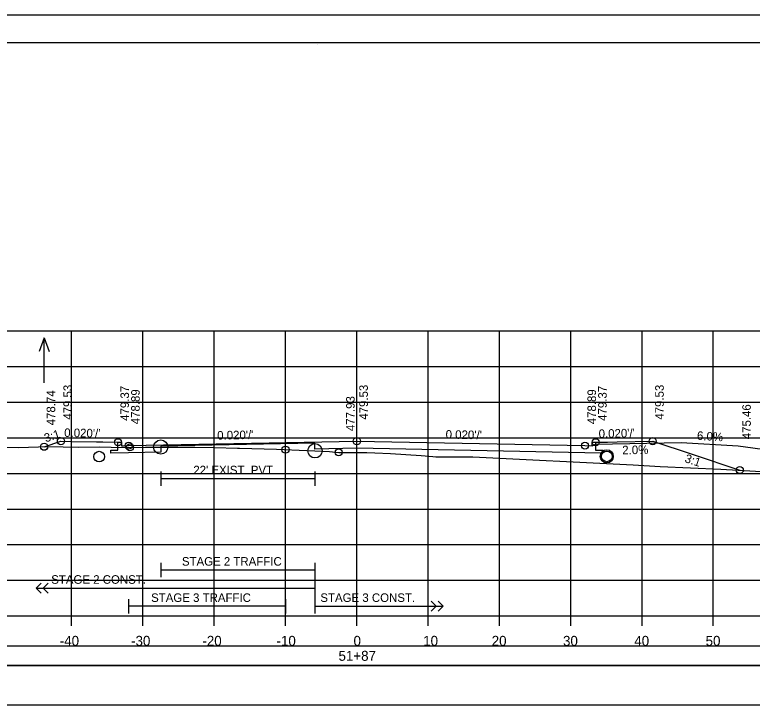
# Model space of a CAD drawing. Extents: x 1371057 to 1372761, y 380005 to 390517.
# Drawn here: x 1371512.9 to 1371616.3, y 383320.8 to 383418.5 of the extents above; entities that cross this region are included whole.
import ezdxf

# ---------------------------------------------------------------- set-up
doc = ezdxf.new("R2010")
doc.units = 0
for name, color, linetype in [('R_Alt Surface', 7, 'Continuous'), ('R_Axis', 7, 'Continuous'), ('R_Axis Annot', 7, 'Continuous'), ('R_Border', 7, 'Continuous'), ('R_Detour', 7, 'Continuous'), ('R_Dimension', 7, 'Continuous'), ('R_Drive', 7, 'Continuous'), ('R_Exist Surface', 7, 'Continuous'), ('R_Fin Surface', 7, 'Continuous'), ('R_Grid', 7, 'Continuous'), ('R_No Plot', 7, 'Continuous'), ('R_Striping', 7, 'Continuous'), ('R_Water', 7, 'Continuous'), ('R_Water Annot', 7, 'Continuous'), ('R_Xsect Elev', 7, 'Continuous'), ('R_Xsect Slope', 7, 'Continuous')]:
    doc.layers.add(name, color=color, linetype=linetype)

msp = doc.modelspace()

# ---------------------------------------------------------------- linework, layer by layer
at = {"layer": 'R_Alt Surface'}
for points in [[(1371594.37, 383358.5), (1371594.37, 383357.42), (1371595.37, 383357.4), (1371595.37, 383356.97), (1371592.87, 383357.02), (1371560.87, 383357.66), (1371555, 383357.54), (1371555, 383358.37), (1371533.37, 383357.94), (1371533.37, 383357.11), (1371528.87, 383357.02), (1371526.37, 383356.97), (1371526.37, 383357.4), (1371527.37, 383357.42), (1371527.37, 383358.5)], [(1371594.37, 383358.49), (1371594.37, 383357.41), (1371595.37, 383357.39), (1371595.37, 383356.96), (1371592.87, 383357.01), (1371560.87, 383357.65), (1371555, 383357.54), (1371555, 383358.37), (1371533.37, 383357.93), (1371533.37, 383357.1), (1371528.87, 383357.01), (1371526.37, 383356.96), (1371526.37, 383357.39), (1371527.37, 383357.41), (1371527.37, 383358.49)], [(1371533.37, 383354.4), (1371533.37, 383352.4)], [(1371555, 383354.4), (1371555, 383352.4)], [(1371533.37, 383353.4), (1371555, 383353.4)]]:
    msp.add_lwpolyline(points, dxfattribs=at)
at = {"layer": 'R_Axis'}
for p, q in [((1371410.87, 383334.13), (1371710.87, 383334.13)), ((1371520.87, 383332.73), (1371520.87, 383334.13)), ((1371530.87, 383332.73), (1371530.87, 383334.13)), ((1371540.87, 383332.73), (1371540.87, 383334.13)), ((1371550.87, 383332.73), (1371550.87, 383334.13)), ((1371560.87, 383332.73), (1371560.87, 383334.13)), ((1371570.87, 383332.73), (1371570.87, 383334.13)), ((1371580.87, 383332.73), (1371580.87, 383334.13)), ((1371590.87, 383332.73), (1371590.87, 383334.13)), ((1371600.87, 383332.73), (1371600.87, 383334.13)), ((1371610.87, 383332.73), (1371610.87, 383334.13))]:
    msp.add_line(p, q, dxfattribs=at)
at = {"layer": 'R_Border'}
for p, q in [((1371402.87, 383414.59), (1371719.05, 383414.59)), ((1371555.39, 383414.33), (1371555.39, 383414.33)), ((1371555.39, 383414.33), (1371555.39, 383414.33))]:
    msp.add_line(p, q, dxfattribs=at)
at = {"layer": 'R_Detour'}
msp.add_lwpolyline([(1371407.72, 383327.18), (1371714.03, 383327.18), (1371714.03, 383329.88), (1371407.72, 383329.88)], close=True, dxfattribs=at)
at = {"layer": 'R_Dimension'}
msp.add_lwpolyline([(1371407.72, 383321.65), (1371714.03, 383321.65), (1371714.03, 383327.18), (1371407.72, 383327.18)], close=True, dxfattribs=at)
at = {"layer": 'R_Drive'}
for p, q in [((1371593.87, 383357.99), (1371594.37, 383358.24)), ((1371594.37, 383358.24), (1371606.37, 383358.48)), ((1371606.37, 383358.48), (1371614.35, 383358.01)), ((1371614.35, 383358.01), (1371622.27, 383356.9))]:
    msp.add_line(p, q, dxfattribs=at)
at = {"layer": 'R_Exist Surface'}
msp.add_lwpolyline([(1371505.26, 383357.79), (1371513.45, 383357.78), (1371517.6, 383357.88), (1371521.8, 383357.8), (1371524.75, 383357.85), (1371526.43, 383357.83), (1371529.05, 383357.78), (1371531.21, 383357.81), (1371533.37, 383357.82), (1371533.44, 383357.82), (1371535.51, 383357.8), (1371538.13, 383357.8), (1371540.93, 383357.75), (1371544.13, 383357.69), (1371544.13, 383357.69), (1371544.24, 383357.69), (1371544.41, 383357.69), (1371549.62, 383357.51), (1371553.85, 383357.35), (1371554.97, 383357.3), (1371555, 383357.3), (1371557.06, 383357.18), (1371558.33, 383357.08), (1371562.28, 383357.05), (1371563.4, 383356.99), (1371565.6, 383356.92), (1371569.9, 383356.63), (1371571.55, 383356.5), (1371571.97, 383356.45), (1371577.02, 383356.44), (1371577.04, 383356.44), (1371577.12, 383356.44), (1371599.64, 383355.33), (1371603.43, 383355.09), (1371611.94, 383354.74), (1371620.05, 383354.25)], dxfattribs=at)
at = {"layer": 'R_Fin Surface'}
msp.add_lwpolyline([(1371517.02, 383357.87), (1371519.37, 383358.65), (1371520.91, 383358.62), (1371524.37, 383358.56), (1371525.25, 383358.54), (1371527.37, 383358.5), (1371527.87, 383358.5), (1371527.88, 383358), (1371528.14, 383358), (1371528.87, 383358.02), (1371560.87, 383358.65), (1371560.87, 383358.65), (1371592.87, 383358.02), (1371592.87, 383358.02), (1371593.87, 383358), (1371593.87, 383358.5), (1371594.37, 383358.5), (1371596.04, 383358.53), (1371597.37, 383358.56), (1371602.37, 383358.65), (1371607.89, 383356.82), (1371614.58, 383354.59)], dxfattribs=at)
at = {"layer": 'R_Grid'}
for p, q in [((1371410.87, 383374.13), (1371710.87, 383374.13)), ((1371520.87, 383334.13), (1371520.87, 383374.13)), ((1371530.87, 383334.13), (1371530.87, 383374.13)), ((1371540.87, 383334.13), (1371540.87, 383374.13)), ((1371550.87, 383334.13), (1371550.87, 383374.13)), ((1371560.87, 383334.13), (1371560.87, 383374.13)), ((1371570.87, 383334.13), (1371570.87, 383374.13)), ((1371580.87, 383334.13), (1371580.87, 383374.13)), ((1371590.87, 383334.13), (1371590.87, 383374.13)), ((1371600.87, 383334.13), (1371600.87, 383374.13)), ((1371610.87, 383334.13), (1371610.87, 383374.13)), ((1371410.87, 383369.13), (1371710.87, 383369.13)), ((1371410.87, 383364.13), (1371710.87, 383364.13)), ((1371410.87, 383359.13), (1371710.87, 383359.13)), ((1371410.87, 383354.13), (1371710.87, 383354.13)), ((1371410.87, 383349.13), (1371710.87, 383349.13)), ((1371410.87, 383344.13), (1371710.87, 383344.13)), ((1371410.87, 383339.13), (1371710.87, 383339.13)), ((1371410.87, 383334.13), (1371710.87, 383334.13))]:
    msp.add_line(p, q, dxfattribs=at)
at = {"layer": 'R_No Plot'}
msp.add_line((1371390.47, 383418.48), (1371723.8, 383418.48), dxfattribs=at)
for points in [[(1371390.46, 383418.48), (1371723.8, 383418.48), (1371723.8, 383205.15), (1371390.46, 383205.15)], [(1371636.79, 383414.59), (1371656.41, 383414.59), (1371656.41, 383404.71), (1371672.52, 383404.71), (1371695.72, 383404.71), (1371695.84, 383376.55), (1371719.05, 383376.55), (1371719.05, 383209.13), (1371402.87, 383209.13), (1371402.87, 383414.59)]]:
    msp.add_lwpolyline(points, close=True, dxfattribs=at)
for centre, radius in [((1371519.37, 383358.65), 0.5), ((1371560.87, 383358.65), 0.5), ((1371602.37, 383358.65), 0.5), ((1371517.02, 383357.87), 0.5), ((1371527.37, 383358.5), 0.5), ((1371528.87, 383358.02), 0.5), ((1371529.05, 383357.78), 0.5), ((1371533.37, 383357.82), 1), ((1371555, 383357.3), 1), ((1371592.87, 383358.02), 0.5), ((1371594.37, 383358.5), 0.5), ((1371550.87, 383357.46), 0.5), ((1371558.33, 383357.08), 0.5), ((1371595.93, 383356.52), 0.917), ((1371614.58, 383354.59), 0.5)]:
    msp.add_circle(centre, radius, dxfattribs=at)
at = {"layer": 'R_Striping'}
for p, q in [((1371533.37, 383341.58), (1371533.37, 383339.58)), ((1371555, 383341.58), (1371555, 383334.49)), ((1371533.37, 383340.58), (1371555, 383340.58)), ((1371515.88, 383338.04), (1371516.59, 383338.74)), ((1371516.88, 383338.04), (1371517.59, 383338.74)), ((1371515.88, 383338.04), (1371555, 383338.04)), ((1371516.59, 383337.33), (1371515.88, 383338.04)), ((1371517.59, 383337.33), (1371516.88, 383338.04)), ((1371528.87, 383336.49), (1371528.87, 383334.49)), ((1371550.87, 383336.49), (1371550.87, 383334.49)), ((1371550.87, 383335.49), (1371528.87, 383335.49)), ((1371555, 383335.49), (1371573, 383335.49)), ((1371555.04, 383335.49), (1371565.04, 383335.49)), ((1371572, 383335.49), (1371571.3, 383336.2)), ((1371571.3, 383334.79), (1371572, 383335.49)), ((1371573, 383335.49), (1371572.3, 383336.2)), ((1371572.3, 383334.79), (1371573, 383335.49))]:
    msp.add_line(p, q, dxfattribs=at)
at = {"layer": 'R_Water'}
for centre in [(1371524.73, 383356.48), (1371595.93, 383356.52)]:
    msp.add_circle(centre, 0.75, dxfattribs=at)
at = {"layer": 'R_Water Annot'}
for p, q in [((1371517.02, 383373.13), (1371516.32, 383371.21)), ((1371517.02, 383366.84), (1371517.02, 383373.13)), ((1371517.02, 383373.13), (1371517.72, 383371.21))]:
    msp.add_line(p, q, dxfattribs=at)
at = {"layer": 'R_Xsect Elev'}
msp.add_line((1371560.87, 383357.06), (1371560.87, 383367.06), dxfattribs=at)

# ---------------------------------------------------------------- texts
at = {"layer": 'R_Axis Annot'}
for s, p in [('-40', (1371519.21, 383329.93)), ('-30', (1371529.21, 383329.93)), ('-20', (1371539.21, 383329.93)), ('-10', (1371549.61, 383329.93)), ('0', (1371560.41, 383329.93)), ('10', (1371570.18, 383329.93)), ('20', (1371579.79, 383329.93)), ('30', (1371589.79, 383329.93)), ('40', (1371599.79, 383329.93)), ('50', (1371609.79, 383329.93)), ('51+87', (1371558.3, 383327.83))]:
    msp.add_text(s, height=1.4, dxfattribs=at).set_placement(p)
at = {"layer": 'R_Striping'}
for s, p in [('STAGE 2 TRAFFIC', (1371536.34, 383341.18)), ('STAGE 2 CONST.', (1371518.01, 383338.64)), ('STAGE 3 TRAFFIC', (1371532.02, 383336.09)), ('STAGE 3 CONST.', (1371555.76, 383336.09))]:
    msp.add_text(s, height=1.2, dxfattribs=at).set_placement(p)
at = {"layer": 'R_Water'}
msp.add_text("22' EXIST. PVT.", height=1.2, dxfattribs=at).set_placement((1371537.94, 383354))
at = {"layer": 'R_Xsect Elev'}
for s, rotation, p in [('479.53', 90, (1371520.92, 383361.66)), ('479.53', 90, (1371562.42, 383361.66)), ('479.53', 90, (1371603.92, 383361.66)), ('478.74', 90, (1371518.57, 383360.87)), ('479.37', 90, (1371528.92, 383361.5)), ('478.89', 90, (1371530.42, 383361.02)), ('478.89', 90, (1371594.42, 383361.02)), ('479.37', 90, (1371595.92, 383361.5)), ('477.93', 90, (1371560.57, 383360.06)), ('475.46', 90, (1371616.13, 383358.92)), ('6.0%', 356.5664, (1371608.55, 383358.85)), ('2.0%', 1.1458, (1371598.11, 383356.8))]:
    msp.add_text(s, height=1.2, rotation=rotation, dxfattribs=at).set_placement(p)
at = {"layer": 'R_Xsect Slope'}
for s, rotation, p in [('3:1', 18.4433, (1371517.25, 383358.47)), ("0.020'/'", 358.8544, (1371519.82, 383359.25)), ("0.020'/'", 1.1458, (1371541.3, 383358.86)), ("0.020'/'", 358.8542, (1371573.32, 383359.01)), ("0.020'/'", 1.1458, (1371594.8, 383359.1)), ('3:1', 341.563, (1371606.77, 383355.74))]:
    msp.add_text(s, height=1.2, rotation=rotation, dxfattribs=at).set_placement(p)

doc.saveas('drawing.dxf')
